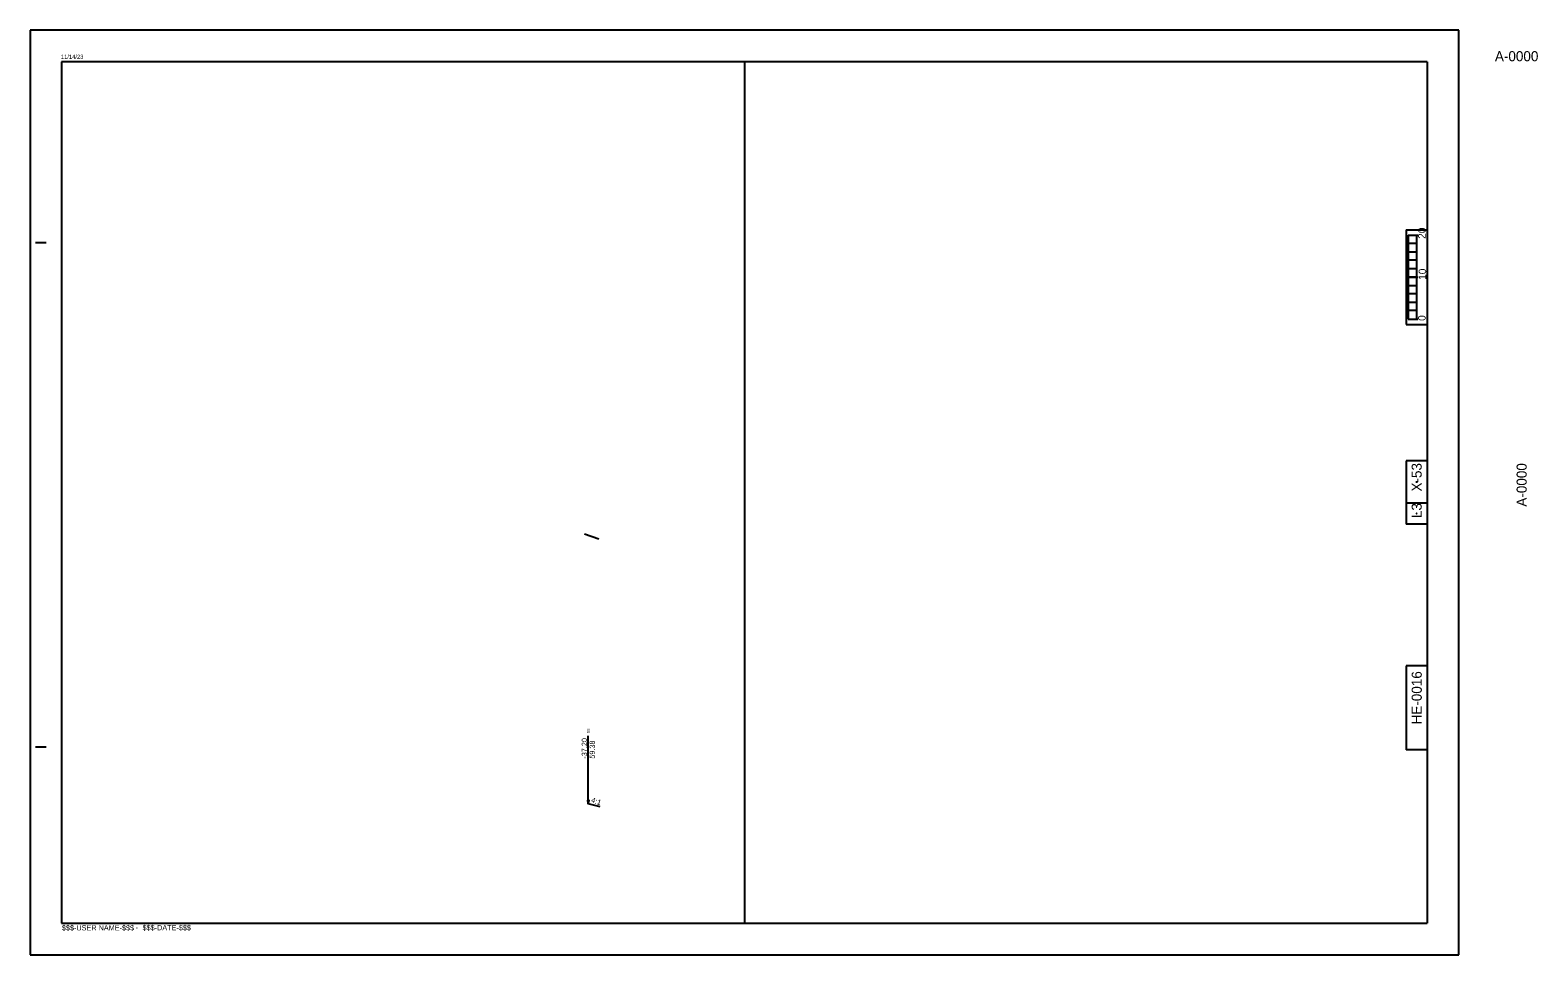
# Model space of a CAD drawing. Extents: x -2.69 to 2.99, y 0 to 1.83.
# Drawn here: x 0 to 2.99, y 0 to 1.833 of the extents above; entities that cross this region are included whole.
import ezdxf

# ---------------------------------------------------------------- set-up
doc = ezdxf.new("R2010")
doc.units = 0
for name, color, linetype in [('Default', 7, 'Continuous'), ('P_NCDOT_XS_Label_Grading_Side_Slope', 7, 'Continuous'), ('P_NCDOT_XS_Leader_Line', 7, 'Continuous'), ('P_NCDOT_XS_Sheet_Alignment_Station_Label', 7, 'Continuous'), ('P_NCDOT_XS_Sheet_Annotation_Label', 7, 'Continuous'), ('P_NCDOT_XS_Sheet_Grid_Border', 7, 'Continuous'), ('Prop XS Grade Point', 7, 'Continuous'), ('Sheet_Grid_Major', 7, 'Continuous'), ('Sheet_Grid_Middle', 7, 'Continuous'), ('Sheet_Grid_Minor', 7, 'Continuous')]:
    doc.layers.add(name, color=color, linetype=linetype)

msp = doc.modelspace()

# ---------------------------------------------------------------- linework, layer by layer
at = {"layer": 'P_NCDOT_XS_Leader_Line'}
msp.add_line((1.107, 0.2992), (1.107, 0.4342), dxfattribs=at)
msp.add_lwpolyline([(1.107, 0.2992), (1.1085, 0.306), (1.1056, 0.306)], close=True, dxfattribs=at)
at = {"layer": 'P_NCDOT_XS_Sheet_Alignment_Station_Label'}
for p, q in [((2.7332, 1.4272), (2.7521, 1.4272)), ((2.7332, 1.4272), (2.7332, 1.2605)), ((2.7416, 1.4272), (2.7503, 1.4272)), ((2.7499, 1.4272), (2.7499, 1.2605)), ((2.7332, 1.3438), (2.7521, 1.3438)), ((2.7332, 1.2605), (2.7521, 1.2605)), ((2.7416, 1.2605), (2.7503, 1.2605))]:
    msp.add_line(p, q, dxfattribs=at)
for points in [[(2.7332, 1.4272), (2.7499, 1.4272), (2.7499, 1.4105), (2.7332, 1.4105)], [(2.7332, 1.3938), (2.7499, 1.3938), (2.7499, 1.3772), (2.7332, 1.3772)], [(2.7332, 1.3605), (2.7499, 1.3605), (2.7499, 1.3438), (2.7332, 1.3438)], [(2.7332, 1.3272), (2.7499, 1.3272), (2.7499, 1.3105), (2.7332, 1.3105)], [(2.7332, 1.2938), (2.7499, 1.2938), (2.7499, 1.2772), (2.7332, 1.2772)]]:
    msp.add_lwpolyline(points, close=True, dxfattribs=at)
at = {"layer": 'P_NCDOT_XS_Sheet_Annotation_Label'}
for p, q in [((1.0992, 0.8345), (1.1277, 0.825)), ((1.1308, 0.2932), (1.107, 0.2992))]:
    msp.add_line(p, q, dxfattribs=at)
at = {"layer": 'Sheet_Grid_Major'}
for p, q in [((2.8333, 1.8333), (0, 1.8333)), ((0, 1.8333), (0, 0)), ((2.8333, 0), (2.8333, 1.8333)), ((1.4167, 1.7708), (1.4166, 0.0625)), ((0, 0), (2.8333, 0))]:
    msp.add_line(p, q, dxfattribs=at)
for centre in [(2.7499, 1.3437), (2.7499, 0.9375), (2.7499, 0.875), (2.75, 0.4897)]:
    msp.add_circle(centre, 0.0001, dxfattribs=at)
at = {"layer": 'Sheet_Grid_Minor'}
for p, q in [((0.0625, 1.7708), (0.0625, 0.0625)), ((2.7708, 1.7708), (0.0625, 1.7708)), ((0.1027, 1.7844), (0.1027, 1.7844)), ((2.7708, 1.7708), (2.7708, 0.0625)), ((2.7292, 1.4375), (2.7292, 1.25)), ((2.7292, 1.4375), (2.7708, 1.4375)), ((0.0108, 1.4125), (0.0317, 1.4126)), ((2.7292, 1.25), (2.7708, 1.25)), ((2.7292, 0.9792), (2.7292, 0.8542)), ((2.7708, 0.9792), (2.7292, 0.9792)), ((2.7708, 0.8958), (2.7292, 0.8958)), ((2.7708, 0.8542), (2.7292, 0.8542)), ((2.7292, 0.5729), (2.7292, 0.4062)), ((2.7708, 0.5729), (2.7292, 0.5729)), ((0.0109, 0.4125), (0.0317, 0.4125)), ((2.7708, 0.4062), (2.7292, 0.4062)), ((0.0625, 0.0625), (2.7708, 0.0625))]:
    msp.add_line(p, q, dxfattribs=at)

# ---------------------------------------------------------------- texts
at = {"layer": 'Default'}
for s, p in [('-37.20', (1.1044, 0.389)), ('59.38', (1.12, 0.389))]:
    msp.add_text(s, height=0.0104, rotation=90, dxfattribs=at).set_placement(p)
at = {"layer": 'P_NCDOT_XS_Label_Grading_Side_Slope'}
msp.add_text('SS', height=0.0052, rotation=270, dxfattribs=at).set_placement((1.1044, 0.4488))
at = {"layer": 'P_NCDOT_XS_Sheet_Alignment_Station_Label'}
for s, p in [('20', (2.7678, 1.4196)), ('10', (2.7688, 1.3382)), ('0', (2.7677, 1.2569))]:
    msp.add_text(s, height=0.015, rotation=90, dxfattribs=at).set_placement(p)
at = {"layer": 'P_NCDOT_XS_Sheet_Grid_Border'}
for s, p in [('X-53', (2.7599, 0.9186)), ('L3', (2.7599, 0.8659))]:
    msp.add_text(s, height=0.02, rotation=90, dxfattribs=at).set_placement(p)
at = {"layer": 'Prop XS Grade Point'}
msp.add_text('4:1', height=0.0104, rotation=341.5651, dxfattribs=at).set_placement((1.1117, 0.3028))
at = {"layer": 'Sheet_Grid_Middle'}
msp.add_text('A-0000', height=0.02, dxfattribs=at).set_placement((2.9051, 1.7717))
for s, p in [('A-0000', (2.9681, 0.8886)), ('HE-0016', (2.76, 0.4568))]:
    msp.add_text(s, height=0.02, rotation=90, dxfattribs=at).set_placement(p)
at = {"layer": 'Sheet_Grid_Minor'}
msp.add_text('11/14/23', height=0.00833, rotation=0, dxfattribs=at).set_placement((0.0609, 1.7764))
for s, height, p in [('$$$-DATE-$$$', 0.010417, (0.223, 0.0486)), ('$$$-USER NAME-$$$', 0.010417, (0.063, 0.0484)), ('-', 0.0104, (0.2093, 0.0494))]:
    msp.add_text(s, height=height, dxfattribs=at).set_placement(p)

doc.saveas('drawing.dxf')
